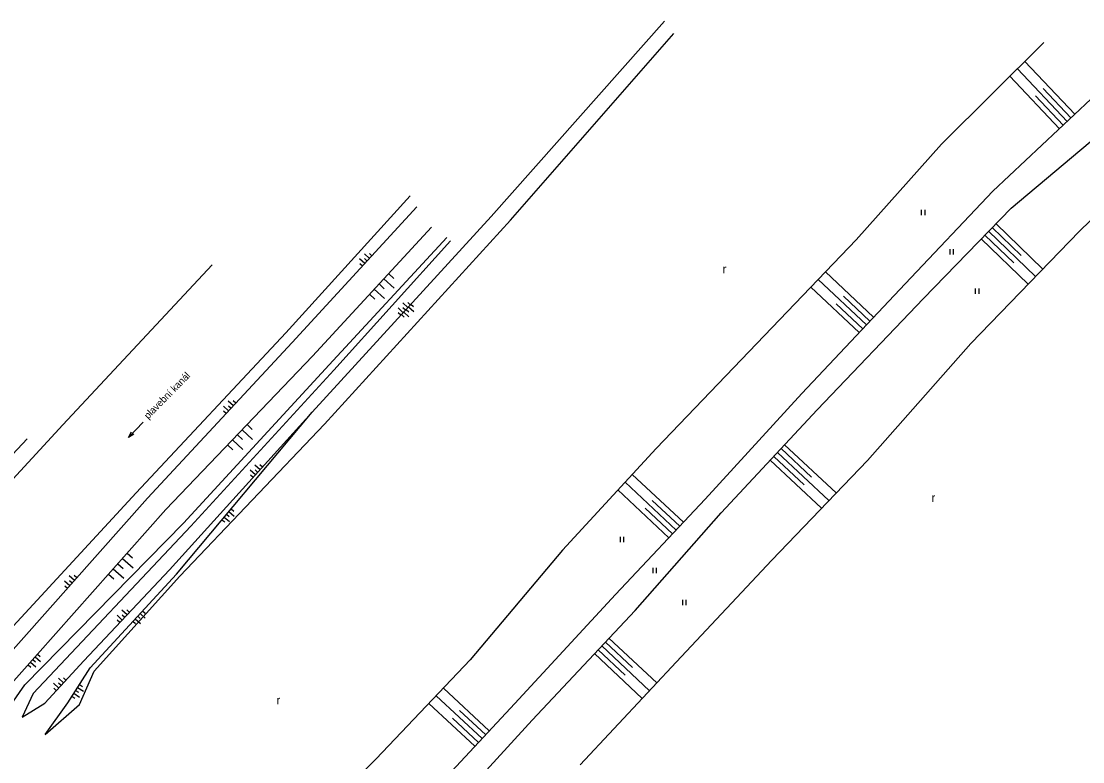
# Model space of a CAD drawing. Extents: x -538441 to -536770, y -1181008 to -1179809.
# Drawn here: x -537652.5 to -537501.6, y -1180010.2 to -1179904.8 of the extents above; entities that cross this region are included whole.
import ezdxf

# ---------------------------------------------------------------- set-up
doc = ezdxf.new("R2010")
doc.units = 0
for name, color, linetype in [('Vrstva 14', 7, 'Continuous'), ('Vrstva 15', 7, 'Continuous'), ('Vrstva 36', 7, 'Continuous'), ('Vrstva 45', 7, 'Continuous')]:
    doc.layers.add(name, color=color, linetype=linetype)

msp = doc.modelspace()

# ---------------------------------------------------------------- linework, layer by layer
at = {"layer": 'Vrstva 14'}
for p, q in [((-537585.71, -1179932.61), (-537561.04, -1179904.82)), ((-537582.96, -1179933.13), (-537559.73, -1179906.57)), ((-537507.08, -1179907.83), (-537521.66, -1179922.33)), ((-537500.42, -1179915.9), (-537514.34, -1179929)), ((-537511.76, -1179931.4), (-537497.95, -1179919.81)), ((-537521.66, -1179922.33), (-537533.78, -1179935.94)), ((-537514.34, -1179929), (-537526.83, -1179942.2)), ((-537597.2, -1179929.66), (-537614.89, -1179949.13)), ((-537613.97, -1179950.54), (-537596.27, -1179931.25)), ((-537524.2, -1179944.26), (-537511.76, -1179931.4)), ((-537611.13, -1179960.44), (-537585.71, -1179932.61)), ((-537609.39, -1179962.14), (-537582.96, -1179933.13)), ((-537611.11, -1179952.47), (-537594.19, -1179934.13)), ((-537608.75, -1179953.71), (-537592.006, -1179935.612)), ((-537591.495, -1179936.085), (-537608.089, -1179954.469)), ((-537533.78, -1179935.94), (-537547.91, -1179950.67)), ((-537503.46, -1179936.16), (-537517.49, -1179950.67)), ((-537625.375, -1179939.479), (-537646.603, -1179962.245)), ((-537526.83, -1179942.2), (-537541.52, -1179957.77)), ((-537539.33, -1179960.12), (-537524.2, -1179944.26)), ((-537614.89, -1179949.13), (-537636.16, -1179971.94)), ((-537634.58, -1179972.69), (-537613.97, -1179950.54)), ((-537547.91, -1179950.67), (-537562.25, -1179965.61)), ((-537517.49, -1179950.67), (-537532.17, -1179967.3)), ((-537631.94, -1179974.3), (-537611.11, -1179952.47)), ((-537629.45, -1179976.24), (-537608.75, -1179953.71)), ((-537608.089, -1179954.469), (-537628.38, -1179976.67)), ((-537541.52, -1179957.77), (-537555.26, -1179972.81)), ((-537631.43, -1179982.86), (-537611.13, -1179960.44)), ((-537630.46, -1179983.47), (-537611.13, -1179960.44)), ((-537553.01, -1179974.77), (-537539.33, -1179960.12)), ((-537646.603, -1179962.245), (-537669.474, -1179986.989)), ((-537629.95, -1179983.75), (-537609.39, -1179962.14)), ((-537662.413, -1179975.691), (-537651.66, -1179964.212)), ((-537562.25, -1179965.61), (-537575.54, -1179980.06)), ((-537532.17, -1179967.3), (-537545.79, -1179981.48)), ((-537636.16, -1179971.94), (-537659.11, -1179996.77)), ((-537657.65, -1179998.68), (-537634.58, -1179972.69)), ((-537555.26, -1179972.81), (-537568.03, -1179986.4)), ((-537655.4, -1180000.75), (-537631.94, -1179974.3)), ((-537565.23, -1179988.65), (-537553.01, -1179974.77)), ((-537652, -1179999.25), (-537629.45, -1179976.24)), ((-537628.38, -1179976.67), (-537650.82, -1180000.48)), ((-537575.54, -1179980.06), (-537588.66, -1179995.67)), ((-537545.79, -1179981.48), (-537558.66, -1179995.23)), ((-537643.62, -1179995.84), (-537631.43, -1179982.86)), ((-537642.73, -1179996.83), (-537630.46, -1179983.47)), ((-537642.14, -1179997.28), (-537629.95, -1179983.75)), ((-537568.03, -1179986.4), (-537582.31, -1180001.87)), ((-537579.88, -1180004.28), (-537565.23, -1179988.65)), ((-537649.17, -1180001.86), (-537643.62, -1179995.84)), ((-537588.66, -1179995.67), (-537602.03, -1180009.75)), ((-537558.66, -1179995.23), (-537573.02, -1180010.61)), ((-537645.91, -1180001.77), (-537642.73, -1179996.83)), ((-537644.24, -1180002.05), (-537642.14, -1179997.28)), ((-537656.03, -1180005.01), (-537652, -1179999.25)), ((-537650.82, -1180000.48), (-537652.38, -1180003.85)), ((-537652.38, -1180003.85), (-537649.17, -1180001.86)), ((-537649.1, -1180006.3), (-537645.91, -1180001.77)), ((-537582.31, -1180001.87), (-537596.41, -1180016.97)), ((-537649.1, -1180006.3), (-537644.24, -1180002.05)), ((-537593.84, -1180019.55), (-537579.88, -1180004.28)), ((-537602.03, -1180009.75), (-537615.95, -1180023.47))]:
    msp.add_line(p, q, dxfattribs=at)
msp.add_lwpolyline([(-537503.46, -1179936.16), (-537502.009, -1179934.667), (-537500.502, -1179933.231), (-537498.941, -1179931.854), (-537497.329, -1179930.539)], dxfattribs=at)
at = {"layer": 'Vrstva 15'}
for p, q in [((-537509.795, -1179910.53), (-537502.712, -1179918.057)), ((-537511.923, -1179912.647), (-537504.897, -1179920.113)), ((-537510.859, -1179911.588), (-537503.804, -1179919.085)), ((-537507.181, -1179914.403), (-537503.258, -1179918.571)), ((-537508.273, -1179915.431), (-537504.35, -1179919.599)), ((-537507.242, -1179940.072), (-537513.91, -1179933.622)), ((-537511.37, -1179939.209), (-537515.474, -1179935.239)), ((-537508.285, -1179941.15), (-537514.953, -1179934.7)), ((-537510.327, -1179938.131), (-537514.431, -1179934.161)), ((-537509.328, -1179942.228), (-537515.995, -1179935.778)), ((-537602.985, -1179938.569), (-537603.722, -1179937.893)), ((-537603.323, -1179938.937), (-537603.691, -1179938.599)), ((-537602.647, -1179938.2), (-537603.015, -1179937.862)), ((-537603.661, -1179939.305), (-537604.398, -1179938.629)), ((-537603.999, -1179939.674), (-537604.367, -1179939.336)), ((-537600.957, -1179941.465), (-537599.487, -1179942.821)), ((-537600.279, -1179940.73), (-537599.544, -1179941.408)), ((-537539.187, -1179941.576), (-537532.338, -1179948.038)), ((-537538.148, -1179940.494), (-537531.308, -1179946.947)), ((-537602.313, -1179942.935), (-537600.843, -1179944.291)), ((-537601.635, -1179942.2), (-537600.9, -1179942.878)), ((-537540.225, -1179942.659), (-537533.367, -1179949.129)), ((-537602.991, -1179943.67), (-537602.256, -1179944.348)), ((-537535.602, -1179943.927), (-537531.823, -1179947.492)), ((-537598.202, -1179946.286), (-537598.941, -1179945.612)), ((-537597.528, -1179945.548), (-537598.267, -1179944.874)), ((-537597.865, -1179945.917), (-537598.234, -1179945.58)), ((-537597.781, -1179945.826), (-537597.412, -1179946.163)), ((-537597.191, -1179945.178), (-537597.56, -1179944.841)), ((-537597.444, -1179945.457), (-537596.705, -1179946.131)), ((-537597.107, -1179945.087), (-537596.738, -1179945.424)), ((-537536.631, -1179945.018), (-537532.852, -1179948.583)), ((-537598.539, -1179946.656), (-537598.908, -1179946.319)), ((-537598.455, -1179946.565), (-537598.086, -1179946.902)), ((-537598.118, -1179946.195), (-537597.379, -1179946.869)), ((-537623.028, -1179960.274), (-537623.76, -1179959.593)), ((-537622.346, -1179959.542), (-537623.079, -1179958.861)), ((-537622.687, -1179959.908), (-537623.053, -1179959.567)), ((-537622.006, -1179959.176), (-537622.372, -1179958.835)), ((-537623.368, -1179960.64), (-537623.734, -1179960.3)), ((-537620.403, -1179962.21), (-537619.68, -1179962.9)), ((-537621.784, -1179963.657), (-537621.06, -1179964.347)), ((-537621.094, -1179962.933), (-537619.646, -1179964.314)), ((-537623.165, -1179965.104), (-537622.441, -1179965.795)), ((-537622.474, -1179964.381), (-537621.027, -1179965.761)), ((-537540.142, -1179969.676), (-537544.475, -1179965.63)), ((-537536.623, -1179971.936), (-537543.963, -1179965.082)), ((-537538.701, -1179974.1), (-537546.011, -1179967.274)), ((-537541.165, -1179970.772), (-537545.499, -1179966.726)), ((-537537.662, -1179973.018), (-537544.987, -1179966.178)), ((-537619.221, -1179969.374), (-537619.962, -1179968.703)), ((-537618.549, -1179968.634), (-537619.291, -1179967.963)), ((-537618.885, -1179969.004), (-537619.255, -1179968.668)), ((-537618.214, -1179968.262), (-537618.584, -1179967.927)), ((-537619.556, -1179969.746), (-537619.926, -1179969.41)), ((-537565.63, -1179969.286), (-537558.364, -1179976.113)), ((-537567.661, -1179971.494), (-537560.418, -1179978.3)), ((-537566.646, -1179970.39), (-537559.391, -1179977.207)), ((-537562.788, -1179972.985), (-537558.878, -1179976.66)), ((-537623.007, -1179974.59), (-537622.24, -1179975.233)), ((-537622.685, -1179974.207), (-537622.303, -1179974.528)), ((-537563.815, -1179974.079), (-537559.905, -1179977.753)), ((-537623.971, -1179975.739), (-537623.588, -1179976.061)), ((-537623.649, -1179975.356), (-537622.883, -1179975.998)), ((-537623.328, -1179974.973), (-537622.945, -1179975.294)), ((-537637.439, -1179980.499), (-537636.691, -1179981.163)), ((-537638.766, -1179981.996), (-537638.018, -1179982.66)), ((-537638.102, -1179981.248), (-537636.606, -1179982.575)), ((-537644.964, -1179984.389), (-537645.712, -1179983.726)), ((-537644.632, -1179984.015), (-537645.006, -1179983.683)), ((-537640.093, -1179983.493), (-537639.345, -1179984.156)), ((-537639.43, -1179982.744), (-537637.933, -1179984.071)), ((-537645.628, -1179985.137), (-537646.376, -1179984.473)), ((-537645.96, -1179985.511), (-537646.333, -1179985.179)), ((-537645.296, -1179984.763), (-537645.67, -1179984.431)), ((-537638.147, -1179990.012), (-537638.877, -1179989.328)), ((-537637.463, -1179989.284), (-537638.192, -1179988.599)), ((-537637.805, -1179989.648), (-537638.169, -1179989.306)), ((-537637.121, -1179988.919), (-537637.485, -1179988.576)), ((-537636.294, -1179989.822), (-537635.557, -1179990.498)), ((-537635.956, -1179989.454), (-537635.588, -1179989.792)), ((-537635.618, -1179989.086), (-537634.881, -1179989.762)), ((-537635.28, -1179988.717), (-537634.912, -1179989.055)), ((-537638.489, -1179990.377), (-537638.854, -1179990.035)), ((-537636.632, -1179990.191), (-537636.264, -1179990.529)), ((-537562.151, -1179998.969), (-537568.939, -1179992.607)), ((-537566.619, -1179997.865), (-537570.478, -1179994.249)), ((-537563.175, -1180000.066), (-537569.965, -1179993.701)), ((-537565.593, -1179996.771), (-537569.452, -1179993.154)), ((-537650.851, -1179995.622), (-537650.477, -1179995.954)), ((-537650.519, -1179995.248), (-537649.771, -1179995.912)), ((-537650.188, -1179994.873), (-537649.814, -1179995.205)), ((-537564.199, -1180001.162), (-537570.991, -1179994.796)), ((-537651.514, -1179996.371), (-537651.141, -1179996.702)), ((-537651.183, -1179995.996), (-537650.434, -1179996.659)), ((-537646.496, -1179998.96), (-537647.232, -1179998.282)), ((-537646.157, -1179998.591), (-537646.525, -1179998.253)), ((-537647.174, -1179999.694), (-537647.909, -1179999.017)), ((-537647.513, -1180000.063), (-537647.88, -1179999.724)), ((-537646.835, -1179999.327), (-537647.202, -1179998.988)), ((-537645.055, -1180000.441), (-537644.213, -1180000.982)), ((-537644.784, -1180000.021), (-537644.364, -1180000.292)), ((-537644.513, -1179999.601), (-537643.672, -1180000.142)), ((-537644.243, -1179999.18), (-537643.823, -1179999.45)), ((-537592.482, -1179999.695), (-537585.963, -1180005.782)), ((-537645.325, -1180000.862), (-537644.905, -1180001.133)), ((-537594.548, -1180001.871), (-537588.011, -1180007.975)), ((-537593.515, -1180000.783), (-537586.987, -1180006.879)), ((-537590.178, -1180002.874), (-537586.475, -1180006.331)), ((-537591.201, -1180003.97), (-537587.499, -1180007.427))]:
    msp.add_line(p, q, dxfattribs=at)
at = {"layer": 'Vrstva 36'}
for p, q in [((-537524.483, -1179932.408), (-537524.483, -1179931.658)), ((-537523.983, -1179932.408), (-537523.983, -1179931.658)), ((-537520.437, -1179938.006), (-537520.437, -1179937.256)), ((-537519.937, -1179938.006), (-537519.937, -1179937.256)), ((-537516.821, -1179943.604), (-537516.821, -1179942.854)), ((-537516.321, -1179943.604), (-537516.321, -1179942.854)), ((-537567.314, -1179978.933), (-537567.314, -1179978.183)), ((-537566.814, -1179978.933), (-537566.814, -1179978.183)), ((-537562.665, -1179983.325), (-537562.665, -1179982.575)), ((-537562.165, -1179983.325), (-537562.165, -1179982.575)), ((-537558.447, -1179987.889), (-537558.447, -1179987.139)), ((-537557.947, -1179987.889), (-537557.947, -1179987.139))]:
    msp.add_line(p, q, dxfattribs=at)
at = {"layer": 'Vrstva 45'}
msp.add_line((-537635.178, -1179961.881), (-537637.277, -1179964.024), dxfattribs=at)
msp.add_lwpolyline([(-537636.5, -1179963.559), (-537637.277, -1179964.024), (-537636.828, -1179963.237)], dxfattribs=at)

# ---------------------------------------------------------------- texts
at = {"layer": 'Vrstva 36'}
for p in [(-537552.783, -1179940.673), (-537523.067, -1179973.199), (-537616.219, -1180002.012)]:
    msp.add_text('r', height=1.2, dxfattribs=at).set_placement(p)
at = {"layer": 'Vrstva 45'}
msp.add_text('plavební kanál', height=1, rotation=45.44626, dxfattribs=at).set_placement((-537634.465, -1179961.486))

doc.saveas('drawing.dxf')
